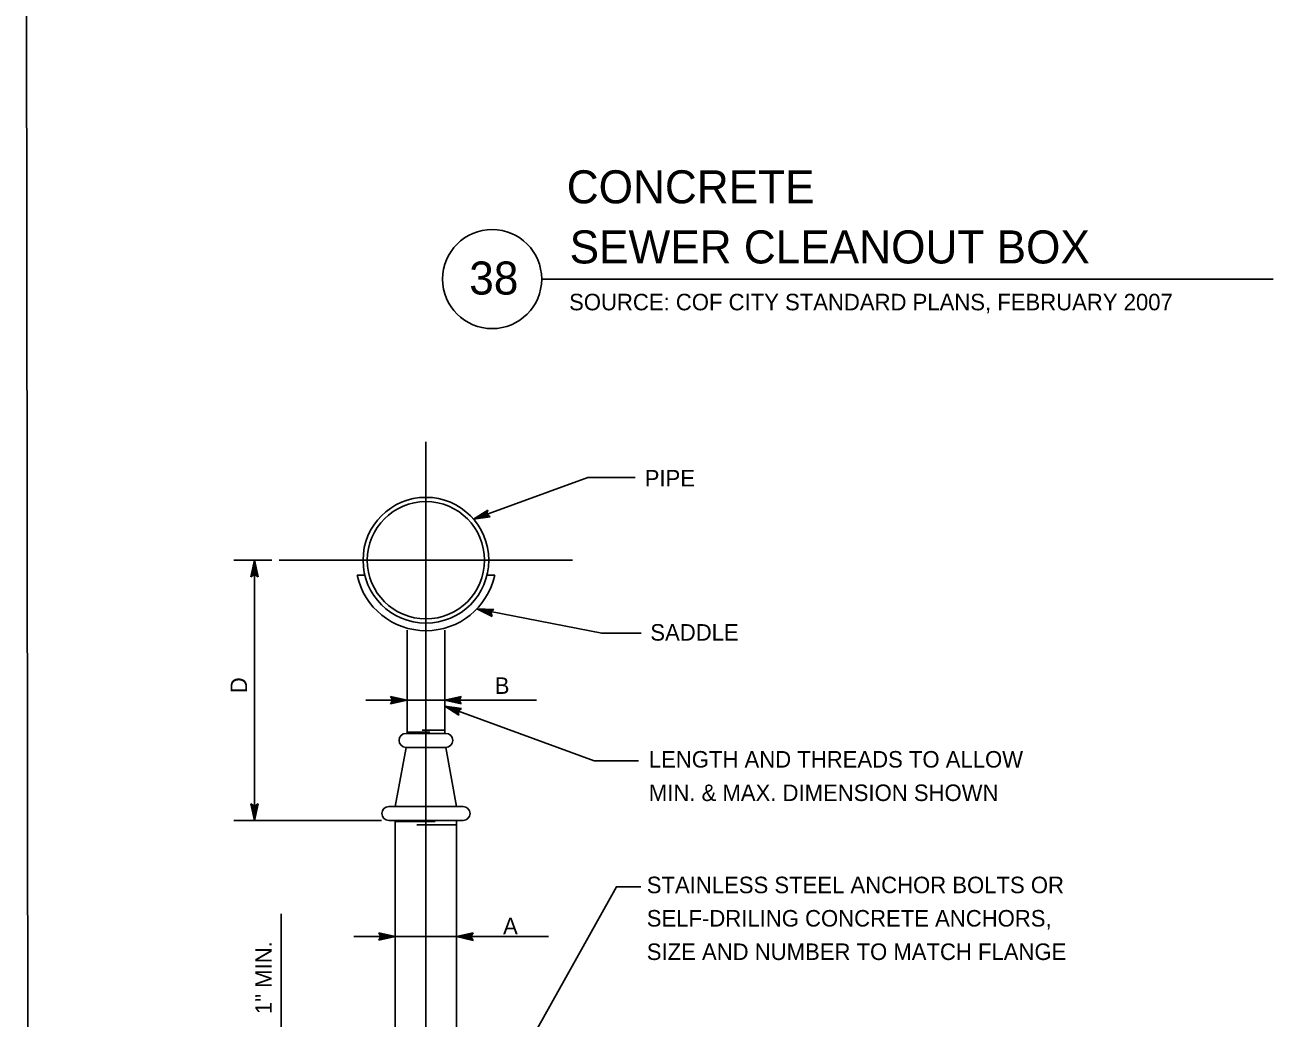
# Model space of a CAD drawing. Extents: x -121875 to -117742, y -103854 to -101122.
# Drawn here: x -121152.3 to -120698.8, y -101904.5 to -101543.8 of the extents above; entities that cross this region are included whole.
import ezdxf

# ---------------------------------------------------------------- set-up
doc = ezdxf.new("R2010")
doc.units = 0
for name, color, linetype in [('G-MARK', 7, 'Continuous'), ('G-TEXT', 7, 'Continuous'), ('Misc CnstDet(22)', 7, 'Continuous')]:
    doc.layers.add(name, color=color, linetype=linetype)

msp = doc.modelspace()

# ---------------------------------------------------------------- linework, layer by layer
at = {"layer": 'G-MARK'}
for p, q in [((-121062.55, -101738.23), (-121076.41, -101738.23)), ((-121068.91, -101832.76), (-121068.91, -101738.23)), ((-121028.44, -101789.01), (-121013.44, -101789.01)), ((-120966.41, -101789.01), (-120999.77, -101789.01)), ((-121022.71, -101832.76), (-121076.41, -101832.76)), ((-121059.15, -101866.71), (-121059.15, -101949.94)), ((-121032.74, -101874.94), (-121017.74, -101874.94)), ((-120962.04, -101874.94), (-120995.47, -101874.94))]:
    msp.add_line(p, q, dxfattribs=at)
for points in [[(-120989.31, -101723.29), (-120947.82, -101708.15), (-120930.63, -101708.15)], [(-120988.05, -101755.84), (-120942.69, -101764.75), (-120928.41, -101764.72)], [(-120999.77, -101791.19), (-120945.52, -101811.07), (-120929.39, -101811.07)], [(-120984.54, -101941.35), (-120937.41, -101856.81), (-120928.5, -101856.81)]]:
    msp.add_lwpolyline(points, dxfattribs=at)
at = {"layer": 'G-TEXT'}
for p, q in [((-120989.31, -101723.29), (-120984.13, -101719.99)), ((-120983.21, -101722.5), (-120989.31, -101723.29)), ((-120989.31, -101723.29), (-120989.31, -101723.29)), ((-120983.54, -101722.24), (-120988.01, -101722.82)), ((-120988, -101722.81), (-120984.22, -101720.41)), ((-120986.71, -101722.35), (-120984.27, -101720.79)), ((-120983.88, -101721.98), (-120986.71, -101722.35)), ((-120985.41, -101721.88), (-120984.37, -101721.21)), ((-120984.16, -101721.71), (-120985.41, -101721.88)), ((-120984.13, -101719.99), (-120984.42, -101721.51)), ((-120984.42, -101721.51), (-120983.21, -101722.5)), ((-120984.13, -101719.99), (-120984.13, -101719.99)), ((-120983.21, -101722.5), (-120983.21, -101722.5)), ((-121070.25, -101744.23), (-121068.91, -101738.23)), ((-121069.9, -101744.01), (-121068.91, -101739.61)), ((-121069.54, -101743.77), (-121068.91, -101740.99)), ((-121068.91, -101738.23), (-121068.91, -101738.23)), ((-121068.91, -101738.23), (-121067.58, -101744.23)), ((-121068.91, -101739.62), (-121067.94, -101743.99)), ((-121068.91, -101740.99), (-121068.29, -101743.81)), ((-121068.91, -101743.43), (-121070.25, -101744.23)), ((-121070.25, -101744.23), (-121070.25, -101744.23)), ((-121069.19, -101743.6), (-121068.91, -101742.37)), ((-121068.91, -101742.37), (-121068.65, -101743.58)), ((-121067.58, -101744.23), (-121068.91, -101743.43)), ((-121067.58, -101744.23), (-121067.58, -101744.23)), ((-120982.58, -101758.64), (-120988.05, -101755.84)), ((-120988.05, -101755.84), (-120988.05, -101755.84)), ((-120988.05, -101755.84), (-120981.91, -101756.06)), ((-120982.7, -101758.24), (-120986.72, -101756.19)), ((-120986.7, -101756.19), (-120982.23, -101756.34)), ((-120982.84, -101757.84), (-120985.38, -101756.54)), ((-120985.38, -101756.54), (-120982.49, -101756.64)), ((-120982.92, -101757.46), (-120984.04, -101756.88)), ((-120984.04, -101756.88), (-120982.8, -101756.93)), ((-120981.91, -101756.06), (-120983.02, -101757.14)), ((-120983.02, -101757.14), (-120982.58, -101758.64)), ((-120982.58, -101758.64), (-120982.58, -101758.64)), ((-120981.91, -101756.06), (-120981.91, -101756.06)), ((-121018.64, -101789.01), (-121019.44, -101787.67)), ((-121019.44, -101787.67), (-121019.44, -101787.67)), ((-121019.44, -101787.67), (-121013.44, -101789.01)), ((-121013.44, -101789.01), (-121019.44, -101790.34)), ((-121019.44, -101790.34), (-121018.64, -101789.01)), ((-121019.44, -101790.34), (-121019.44, -101790.34)), ((-121019.23, -101788.02), (-121014.82, -101789.01)), ((-121014.83, -101789.01), (-121019.21, -101789.98)), ((-121016.21, -101789), (-121019.03, -101789.63)), ((-121018.99, -101788.38), (-121016.21, -101789)), ((-121018.82, -101788.73), (-121017.59, -101789)), ((-121017.59, -101789), (-121018.8, -101789.27)), ((-121013.44, -101789.01), (-121013.44, -101789.01)), ((-120999.77, -101789.01), (-120993.77, -101787.68)), ((-120993.77, -101790.35), (-120999.77, -101789.01)), ((-120999.77, -101789.01), (-120999.77, -101789.01)), ((-120994.62, -101794.55), (-120999.77, -101791.19)), ((-120999.77, -101791.19), (-120999.77, -101791.19)), ((-120999.77, -101791.19), (-120993.68, -101792.05)), ((-120993.99, -101789.99), (-120998.39, -101789.01)), ((-120998.38, -101789), (-120994.01, -101788.04)), ((-120997.01, -101789.01), (-120994.18, -101788.38)), ((-120994.22, -101789.63), (-120997.01, -101789.01)), ((-120995.63, -101789.01), (-120994.42, -101788.74)), ((-120994.4, -101789.28), (-120995.63, -101789.01)), ((-120993.77, -101787.68), (-120994.57, -101789.01)), ((-120994.57, -101789.01), (-120993.77, -101790.35)), ((-120993.77, -101787.68), (-120993.77, -101787.68)), ((-120993.77, -101790.35), (-120993.77, -101790.35)), ((-120994.7, -101794.14), (-120998.48, -101791.68)), ((-120998.47, -101791.68), (-120994.03, -101792.3)), ((-120994.79, -101793.72), (-120997.18, -101792.16)), ((-120997.18, -101792.16), (-120994.32, -101792.57)), ((-120994.83, -101793.34), (-120995.89, -101792.65)), ((-120995.89, -101792.65), (-120994.66, -101792.82)), ((-120993.68, -101792.05), (-120994.9, -101793.01)), ((-120994.9, -101793.01), (-120994.62, -101794.55)), ((-120994.62, -101794.55), (-120994.62, -101794.55)), ((-120993.68, -101792.05), (-120993.68, -101792.05)), ((-121068.91, -101832.76), (-121070.24, -101826.76)), ((-121070.24, -101826.76), (-121070.24, -101826.76)), ((-121070.24, -101826.76), (-121068.91, -101827.56)), ((-121068.91, -101831.37), (-121069.88, -101826.99)), ((-121068.91, -101829.99), (-121069.54, -101827.17)), ((-121068.91, -101828.61), (-121069.18, -101827.4)), ((-121068.91, -101827.56), (-121067.57, -101826.76)), ((-121067.57, -101826.76), (-121068.91, -101832.76)), ((-121067.93, -101826.97), (-121068.91, -101831.38)), ((-121068.29, -101827.21), (-121068.91, -101829.99)), ((-121068.63, -101827.38), (-121068.91, -101828.61)), ((-121067.57, -101826.76), (-121067.57, -101826.76)), ((-121068.91, -101832.76), (-121068.91, -101832.76)), ((-121022.94, -101874.94), (-121023.74, -101873.6)), ((-121023.74, -101873.6), (-121023.74, -101873.6)), ((-121023.74, -101873.6), (-121017.74, -101874.94)), ((-121017.74, -101874.94), (-121023.74, -101876.27)), ((-121023.74, -101876.27), (-121022.94, -101874.94)), ((-121023.74, -101876.27), (-121023.74, -101876.27)), ((-121023.52, -101873.96), (-121019.12, -101874.94)), ((-121019.13, -101874.95), (-121023.5, -101875.91)), ((-121020.5, -101874.94), (-121023.33, -101875.57)), ((-121023.29, -101874.32), (-121020.5, -101874.94)), ((-121023.11, -101874.67), (-121021.88, -101874.94)), ((-121021.88, -101874.94), (-121023.09, -101875.21)), ((-121017.74, -101874.94), (-121017.74, -101874.94)), ((-120995.47, -101874.94), (-120989.47, -101873.61)), ((-120989.47, -101876.28), (-120995.47, -101874.94)), ((-120995.47, -101874.94), (-120995.47, -101874.94)), ((-120989.69, -101875.93), (-120994.09, -101874.94)), ((-120994.08, -101874.94), (-120989.71, -101873.97)), ((-120992.71, -101874.95), (-120989.89, -101874.32)), ((-120989.92, -101875.57), (-120992.71, -101874.95)), ((-120991.33, -101874.95), (-120990.12, -101874.68)), ((-120990.1, -101875.22), (-120991.33, -101874.95)), ((-120989.47, -101873.61), (-120990.27, -101874.94)), ((-120990.27, -101874.94), (-120989.47, -101876.28)), ((-120989.47, -101873.61), (-120989.47, -101873.61)), ((-120989.47, -101876.28), (-120989.47, -101876.28))]:
    msp.add_line(p, q, dxfattribs=at)
at = {"layer": 'Misc CnstDet(22)'}
for p, q in [((-121152.3, -101153.11), (-121150.94, -102136.14)), ((-120964.55, -101636.1), (-120698.8, -101636.1)), ((-121006.61, -101955.02), (-121006.61, -101695.26)), ((-121059.93, -101738.23), (-120953.29, -101738.23)), ((-121031.6, -101743.69), (-121028.79, -101743.69)), ((-120984.42, -101743.69), (-120981.61, -101743.69)), ((-121013.44, -101801.12), (-121013.44, -101763.62)), ((-120999.77, -101801.12), (-120999.77, -101763.62)), ((-121013.44, -101787.73), (-121013.44, -101796.51)), ((-121013.44, -101789.01), (-120999.77, -101789.01)), ((-120999.77, -101787.73), (-120999.77, -101796.51)), ((-120999.77, -101799.94), (-121007.97, -101799.94)), ((-121013.83, -101801.12), (-120999.38, -101801.12)), ((-121005.24, -101800.73), (-121013.44, -101800.73)), ((-121013.83, -101806.19), (-121017.74, -101827.68)), ((-121013.83, -101806.19), (-120999.38, -101806.19)), ((-120999.38, -101806.19), (-120995.47, -101827.68)), ((-121020.08, -101827.68), (-120993.13, -101827.68)), ((-121020.08, -101832.76), (-120993.13, -101832.76)), ((-121017.74, -101944.87), (-121017.74, -101832.76)), ((-121003.29, -101833.15), (-121017.74, -101833.15)), ((-120995.47, -101834.32), (-121009.93, -101834.32)), ((-120995.47, -101944.87), (-120995.47, -101832.76)), ((-121017.74, -101874.44), (-121017.74, -101882.44)), ((-121017.74, -101874.94), (-120995.47, -101874.94)), ((-120995.47, -101874.44), (-120995.47, -101882.44))]:
    msp.add_line(p, q, dxfattribs=at)
for centre, radius in [((-120982.55, -101636.1), 18), ((-121006.61, -101738.23), 22.85), ((-121006.61, -101738.23), 21.29)]:
    msp.add_circle(centre, radius, dxfattribs=at)
for centre, radius, start, end in [((-121006.61, -101738.23), 25.59, 192.3416, 347.6584), ((-121013.83, -101803.65), 2.54, 90, 270), ((-120999.38, -101803.65), 2.54, 270, 90), ((-121020.08, -101830.22), 2.54, 90, 270), ((-120993.13, -101830.22), 2.54, 270, 90)]:
    msp.add_arc(centre, radius, start, end, dxfattribs=at)

# ---------------------------------------------------------------- texts
for s, height, p in [('CONCRETE', 12, (-120955.43, -101608.6)), ('SEWER CLEANOUT BOX', 12, (-120954.39, -101630.43)), ('38', 12, (-120990.86, -101641.73)), ('SOURCE: COF CITY STANDARD PLANS, FEBRUARY 2007', 6, (-120954.58, -101647.45)), ('PIPE', 6, (-120927.11, -101711.43)), ('SADDLE', 6, (-120925.07, -101767.43)), ('B', 6, (-120981.61, -101786.76)), ('LENGTH AND THREADS TO ALLOW', 6, (-120925.61, -101813.53)), ('MIN. & MAX. DIMENSION SHOWN', 6, (-120925.61, -101825.68)), ('STAINLESS STEEL ANCHOR BOLTS OR', 6, (-120926.36, -101859.16)), ('A', 6, (-120978.58, -101874.08)), ('SELF-DRILING CONCRETE ANCHORS,', 6, (-120926.36, -101871.27)), ('SIZE AND NUMBER TO MATCH FLANGE', 6, (-120926.36, -101883.42))]:
    msp.add_text(s, height=height, dxfattribs=at).set_placement(p)
for s, p in [('D', (-121071.61, -101786.55)), ('1" MIN.', (-121062.6, -101903.07))]:
    msp.add_text(s, height=6, rotation=90, dxfattribs=at).set_placement(p)

doc.saveas('drawing.dxf')
